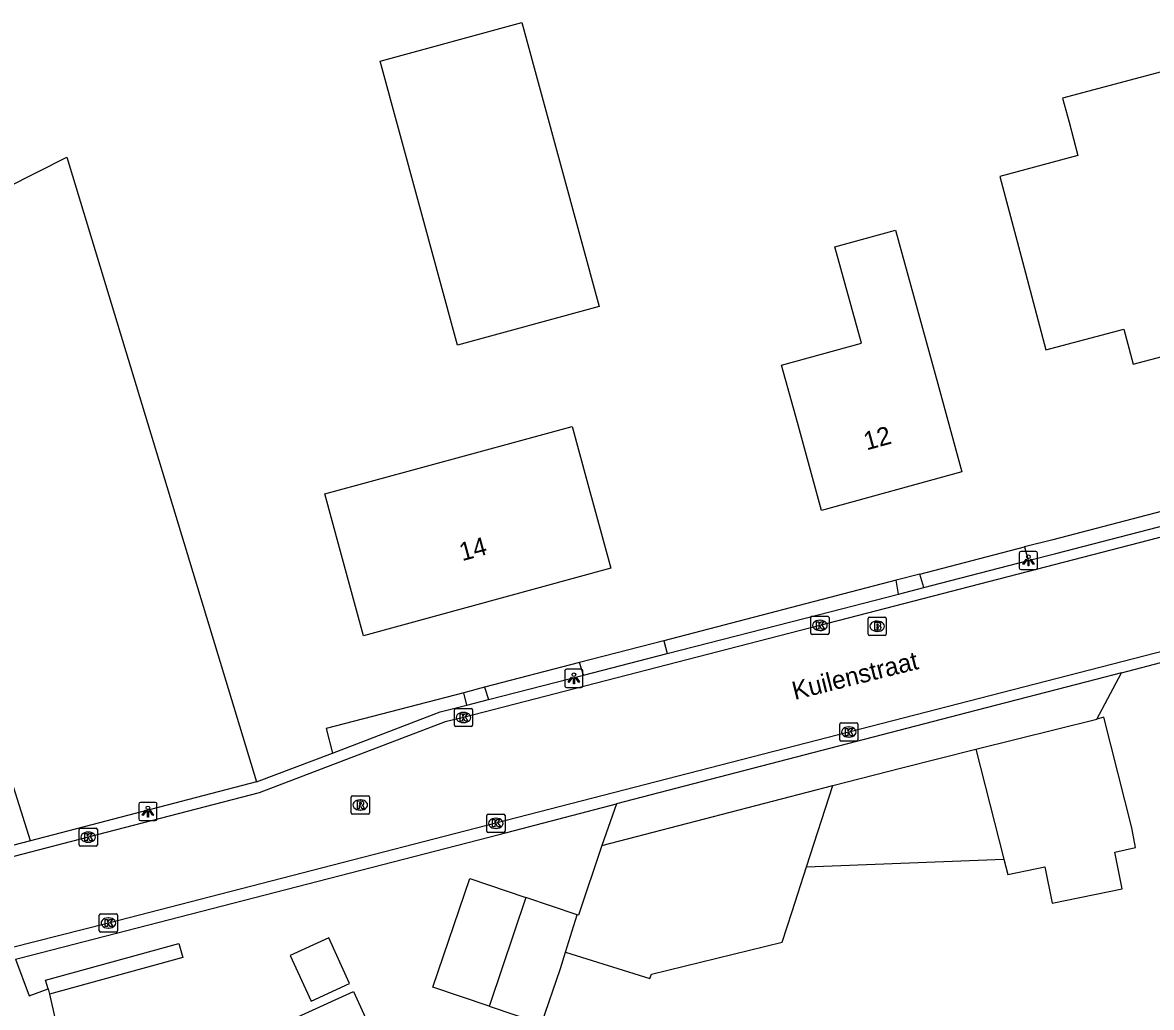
# Model space of a CAD drawing. Extents: x 162880 to 165536, y 384011 to 385179.
# Drawn here: x 163777.7 to 163839.6, y 384622 to 384676.1 of the extents above; entities that cross this region are included whole.
import ezdxf

# ---------------------------------------------------------------- set-up
doc = ezdxf.new("R2010")
doc.units = 0
for name, color, linetype in [('IMGEO_Brandkraan', 7, 'Continuous'), ('IMGEO_Groenvoorziening', 7, 'Continuous'), ('IMGEO_Haag', 7, 'Continuous'), ('IMGEO_Kolk', 7, 'Continuous'), ('IMGEO_Lichtpunt', 7, 'Continuous'), ('IMGEO_Openbare_ruimte_label', 7, 'Continuous'), ('IMGEO_Pand', 7, 'Continuous'), ('IMGEO_Pand_nummerreeks', 7, 'Continuous'), ('IMGEO_Rijbaan_lokaal_open', 7, 'Continuous'), ('IMGEO_Rioolput', 7, 'Continuous'), ('IMGEO_Voetpad_halfverhard', 7, 'Continuous'), ('IMGEO_Voetpad_open', 7, 'Continuous')]:
    doc.layers.add(name, color=color, linetype=linetype)

msp = doc.modelspace()

# ---------------------------------------------------------------- linework, layer by layer
at = {"layer": 'IMGEO_Brandkraan'}
for p, q in [((163824.029, 384642.526), (163824.029, 384643.378)), ((163824.104, 384643.452), (163824.956, 384643.452)), ((163824.517, 384643.232), (163824.542, 384643.232)), ((163825.03, 384643.378), (163825.03, 384642.526)), ((163824.54, 384642.672), (163824.515, 384642.672)), ((163824.956, 384642.452), (163824.104, 384642.452))]:
    msp.add_line(p, q, dxfattribs=at)
for points in [[(163824.029, 384642.526), (163824.029, 384643.378)], [(163824.104, 384643.452), (163824.956, 384643.452)], [(163824.377, 384643.152), (163824.377, 384642.752), (163824.59, 384642.752)], [(163824.608, 384643.152), (163824.377, 384643.152)], [(163825.03, 384643.378), (163825.03, 384642.526)], [(163824.556, 384643.071), (163824.502, 384643.071), (163824.502, 384642.995)], [(163824.502, 384642.995), (163824.555, 384642.995)], [(163824.564, 384642.919), (163824.502, 384642.919), (163824.502, 384642.838)], [(163824.502, 384642.838), (163824.564, 384642.838)], [(163824.956, 384642.452), (163824.104, 384642.452)]]:
    msp.add_lwpolyline(points, dxfattribs=at)
for centre, radius, start, end in [((163824.106, 384643.376), 0.0765, 91.55205, 178.44795), ((163824.106, 384643.376), 0.0765, 91.55205, 178.44795), ((163824.612, 384643.007), 0.145, 59.4692, 91.53667), ((163824.637, 384643.054), 0.0922, 285.51372, 58.15012), ((163824.954, 384643.376), 0.0765, 1.55205, 88.44795), ((163824.954, 384643.376), 0.0765, 1.55205, 88.44795), ((163824.106, 384642.528), 0.0765, 181.55205, 268.44795), ((163824.106, 384642.528), 0.0765, 181.55205, 268.44795), ((163824.557, 384643.033), 0.0379, 267.82845, 90.93552), ((163824.565, 384642.878), 0.0404, 269.87594, 90.50774), ((163824.596, 384643.003), 0.251, 268.66757, 293.53466), ((163824.642, 384642.862), 0.105, 301.31148, 78.98903), ((163824.954, 384642.528), 0.0765, 271.55205, 358.44795), ((163824.954, 384642.528), 0.0765, 271.55205, 358.44795)]:
    msp.add_arc(centre, radius, start, end, dxfattribs=at)
for centre, major_axis, ratio, start_param, end_param in [((163824.516, 384642.952), (-0.387, 0.002), 0.722429, 4.712389, 7.853982), ((163824.541, 384642.952), (-0.39, 0.002), 0.717154, 1.570796, 4.712389)]:
    msp.add_ellipse(centre, major_axis=major_axis, ratio=ratio, start_param=start_param, end_param=end_param, dxfattribs=at)
at = {"layer": 'IMGEO_Groenvoorziening'}
for points in [[(163776.799, 384667.029), (163780.094, 384668.687), (163790.492, 384634.412)], [(163778.093, 384631.181), (163768.177, 384662.661), (163766.054, 384662.013), (163765.695, 384663.191)], [(163808.212, 384640.956), (163803.003, 384639.602)]]:
    msp.add_lwpolyline(points, dxfattribs=at)
at = {"layer": 'IMGEO_Haag'}
for points in [[(163845.271, 384650.593), (163834.156, 384647.702), (163832.611, 384647.3)], [(163825.578, 384645.472), (163812.821, 384642.155)], [(163801.865, 384639.306), (163794.32, 384637.344), (163794.651, 384635.997)], [(163779.074, 384623.056), (163778.928, 384623.543), (163786.235, 384625.552), (163786.447, 384624.78), (163779.139, 384622.771)]]:
    msp.add_lwpolyline(points, dxfattribs=at)
at = {"layer": 'IMGEO_Kolk'}
for p, q in [((163820.889, 384642.572), (163820.889, 384643.424)), ((163820.964, 384643.498), (163821.816, 384643.498)), ((163821.377, 384643.278), (163821.402, 384643.278)), ((163821.89, 384643.424), (163821.89, 384642.572)), ((163821.816, 384642.498), (163820.964, 384642.498)), ((163821.4, 384642.718), (163821.375, 384642.718)), ((163801.341, 384637.521), (163801.341, 384638.373)), ((163801.416, 384638.447), (163802.268, 384638.447)), ((163801.829, 384638.227), (163801.854, 384638.227)), ((163802.342, 384638.373), (163802.342, 384637.521)), ((163801.852, 384637.667), (163801.827, 384637.667)), ((163822.474, 384636.723), (163822.474, 384637.575)), ((163822.549, 384637.649), (163823.401, 384637.649)), ((163823.475, 384637.575), (163823.475, 384636.723)), ((163802.268, 384637.447), (163801.416, 384637.447)), ((163822.962, 384637.429), (163822.987, 384637.429)), ((163823.401, 384636.649), (163822.549, 384636.649)), ((163822.985, 384636.869), (163822.96, 384636.869)), ((163803.119, 384631.717), (163803.119, 384632.569)), ((163803.194, 384632.643), (163804.046, 384632.643)), ((163804.12, 384632.569), (163804.12, 384631.717)), ((163803.607, 384632.423), (163803.632, 384632.423)), ((163780.763, 384630.957), (163780.763, 384631.809)), ((163780.838, 384631.883), (163781.69, 384631.883)), ((163781.251, 384631.663), (163781.276, 384631.663)), ((163781.764, 384631.809), (163781.764, 384630.957)), ((163804.046, 384631.643), (163803.194, 384631.643)), ((163803.63, 384631.863), (163803.605, 384631.863)), ((163781.69, 384630.883), (163780.838, 384630.883)), ((163781.274, 384631.103), (163781.249, 384631.103)), ((163781.868, 384626.247), (163781.868, 384627.099)), ((163781.943, 384627.173), (163782.795, 384627.173)), ((163782.869, 384627.099), (163782.869, 384626.247)), ((163782.379, 384626.393), (163782.354, 384626.393)), ((163782.356, 384626.953), (163782.381, 384626.953)), ((163782.795, 384626.173), (163781.943, 384626.173))]:
    msp.add_line(p, q, dxfattribs=at)
for points in [[(163820.889, 384642.572), (163820.889, 384643.424)], [(163820.964, 384643.498), (163821.816, 384643.498)], [(163821.21, 384643.198), (163821.333, 384643.198), (163821.333, 384643.047), (163821.463, 384643.198), (163821.627, 384643.198), (163821.481, 384643.047), (163821.634, 384642.798), (163821.482, 384642.798), (163821.397, 384642.962), (163821.333, 384642.895), (163821.333, 384642.798), (163821.21, 384642.798), (163821.21, 384643.198)], [(163821.89, 384643.424), (163821.89, 384642.572)], [(163821.816, 384642.498), (163820.964, 384642.498)], [(163801.341, 384637.521), (163801.341, 384638.373)], [(163801.416, 384638.447), (163802.268, 384638.447)], [(163801.662, 384638.147), (163801.785, 384638.147), (163801.785, 384637.996), (163801.915, 384638.147), (163802.079, 384638.147), (163801.933, 384637.996), (163802.086, 384637.747), (163801.934, 384637.747), (163801.849, 384637.911), (163801.785, 384637.844), (163801.785, 384637.747), (163801.662, 384637.747), (163801.662, 384638.147)], [(163802.342, 384638.373), (163802.342, 384637.521)], [(163822.474, 384636.723), (163822.474, 384637.575)], [(163822.549, 384637.649), (163823.401, 384637.649)], [(163823.475, 384637.575), (163823.475, 384636.723)], [(163802.268, 384637.447), (163801.416, 384637.447)], [(163822.795, 384637.349), (163822.918, 384637.349), (163822.918, 384637.198), (163823.048, 384637.349), (163823.212, 384637.349), (163823.066, 384637.198), (163823.219, 384636.949), (163823.067, 384636.949), (163822.982, 384637.113), (163822.918, 384637.046), (163822.918, 384636.949), (163822.795, 384636.949), (163822.795, 384637.349)], [(163823.401, 384636.649), (163822.549, 384636.649)], [(163803.119, 384631.717), (163803.119, 384632.569)], [(163803.194, 384632.643), (163804.046, 384632.643)], [(163804.12, 384632.569), (163804.12, 384631.717)], [(163803.44, 384632.343), (163803.563, 384632.343), (163803.563, 384632.192), (163803.693, 384632.343), (163803.857, 384632.343), (163803.711, 384632.192), (163803.864, 384631.943), (163803.712, 384631.943), (163803.627, 384632.107), (163803.563, 384632.04), (163803.563, 384631.943), (163803.44, 384631.943), (163803.44, 384632.343)], [(163780.763, 384630.957), (163780.763, 384631.809)], [(163780.838, 384631.883), (163781.69, 384631.883)], [(163781.084, 384631.583), (163781.207, 384631.583), (163781.207, 384631.432), (163781.337, 384631.583), (163781.501, 384631.583), (163781.355, 384631.432), (163781.508, 384631.183), (163781.356, 384631.183), (163781.271, 384631.347), (163781.207, 384631.28), (163781.207, 384631.183), (163781.084, 384631.183), (163781.084, 384631.583)], [(163781.764, 384631.809), (163781.764, 384630.957)], [(163804.046, 384631.643), (163803.194, 384631.643)], [(163781.69, 384630.883), (163780.838, 384630.883)], [(163781.868, 384626.247), (163781.868, 384627.099)], [(163781.943, 384627.173), (163782.795, 384627.173)], [(163782.869, 384627.099), (163782.869, 384626.247)], [(163782.189, 384626.873), (163782.312, 384626.873), (163782.312, 384626.722), (163782.442, 384626.873), (163782.606, 384626.873), (163782.46, 384626.722), (163782.613, 384626.473), (163782.461, 384626.473), (163782.376, 384626.637), (163782.312, 384626.57), (163782.312, 384626.473), (163782.189, 384626.473), (163782.189, 384626.873)], [(163782.795, 384626.173), (163781.943, 384626.173)]]:
    msp.add_lwpolyline(points, dxfattribs=at)
for centre, start, end in [((163820.966, 384643.422), 91.55205, 178.44795), ((163820.966, 384643.422), 91.55205, 178.44795), ((163821.814, 384643.422), 1.55205, 88.44795), ((163821.814, 384643.422), 1.55205, 88.44795), ((163820.966, 384642.574), 181.55205, 268.44795), ((163820.966, 384642.574), 181.55205, 268.44795), ((163821.814, 384642.574), 271.55205, 358.44795), ((163821.814, 384642.574), 271.55205, 358.44795), ((163801.418, 384638.371), 91.55205, 178.44795), ((163801.418, 384638.371), 91.55205, 178.44795), ((163802.266, 384638.371), 1.55205, 88.44795), ((163802.266, 384638.371), 1.55205, 88.44795), ((163801.418, 384637.523), 181.55205, 268.44795), ((163801.418, 384637.523), 181.55205, 268.44795), ((163802.266, 384637.523), 271.55205, 358.44795), ((163802.266, 384637.523), 271.55205, 358.44795), ((163822.551, 384637.573), 91.55205, 178.44795), ((163822.551, 384637.573), 91.55205, 178.44795), ((163823.399, 384637.573), 1.55205, 88.44795), ((163823.399, 384637.573), 1.55205, 88.44795), ((163822.551, 384636.725), 181.55205, 268.44795), ((163822.551, 384636.725), 181.55205, 268.44795), ((163823.399, 384636.725), 271.55205, 358.44795), ((163823.399, 384636.725), 271.55205, 358.44795), ((163803.196, 384632.567), 91.55205, 178.44795), ((163803.196, 384632.567), 91.55205, 178.44795), ((163804.044, 384632.567), 1.55205, 88.44795), ((163804.044, 384632.567), 1.55205, 88.44795), ((163780.84, 384631.807), 91.55205, 178.44795), ((163780.84, 384631.807), 91.55205, 178.44795), ((163781.688, 384631.807), 1.55205, 88.44795), ((163781.688, 384631.807), 1.55205, 88.44795), ((163803.196, 384631.719), 181.55205, 268.44795), ((163803.196, 384631.719), 181.55205, 268.44795), ((163804.044, 384631.719), 271.55205, 358.44795), ((163804.044, 384631.719), 271.55205, 358.44795), ((163780.84, 384630.959), 181.55205, 268.44795), ((163780.84, 384630.959), 181.55205, 268.44795), ((163781.688, 384630.959), 271.55205, 358.44795), ((163781.688, 384630.959), 271.55205, 358.44795), ((163781.945, 384627.097), 91.55205, 178.44795), ((163781.945, 384627.097), 91.55205, 178.44795), ((163782.793, 384627.097), 1.55205, 88.44795), ((163782.793, 384627.097), 1.55205, 88.44795), ((163781.945, 384626.249), 181.55205, 268.44795), ((163781.945, 384626.249), 181.55205, 268.44795), ((163782.793, 384626.249), 271.55205, 358.44795), ((163782.793, 384626.249), 271.55205, 358.44795)]:
    msp.add_arc(centre, 0.0765, start, end, dxfattribs=at)
for centre, major_axis, ratio, start_param, end_param in [((163821.376, 384642.998), (-0.387, 0.002), 0.722429, 4.712389, 7.853982), ((163821.401, 384642.998), (-0.39, 0.002), 0.717154, 1.570796, 4.712389), ((163801.828, 384637.947), (-0.387, 0.002), 0.722429, 4.712389, 7.853982), ((163801.853, 384637.947), (-0.39, 0.002), 0.717154, 1.570796, 4.712389), ((163822.961, 384637.149), (-0.387, 0.002), 0.722429, 4.712389, 7.853982), ((163822.986, 384637.149), (-0.39, 0.002), 0.717154, 1.570796, 4.712389), ((163803.606, 384632.143), (-0.387, 0.002), 0.722429, 4.712389, 7.853982), ((163803.631, 384632.143), (-0.39, 0.002), 0.717154, 1.570796, 4.712389), ((163781.25, 384631.383), (-0.387, 0.002), 0.722429, 4.712389, 7.853982), ((163781.275, 384631.383), (-0.39, 0.002), 0.717154, 1.570796, 4.712389), ((163782.355, 384626.673), (-0.387, 0.002), 0.722429, 4.712389, 7.853982), ((163782.38, 384626.673), (-0.39, 0.002), 0.717154, 1.570796, 4.712389)]:
    msp.add_ellipse(centre, major_axis=major_axis, ratio=ratio, start_param=start_param, end_param=end_param, dxfattribs=at)
at = {"layer": 'IMGEO_Lichtpunt'}
for p, q in [((163832.324, 384646.966), (163832.324, 384646.159)), ((163832.324, 384646.966), (163832.324, 384646.159)), ((163833.226, 384647.061), (163832.418, 384647.061)), ((163833.226, 384647.061), (163832.418, 384647.061)), ((163833.32, 384646.159), (163833.32, 384646.966)), ((163833.32, 384646.159), (163833.32, 384646.966)), ((163832.418, 384646.065), (163833.226, 384646.065)), ((163832.418, 384646.065), (163833.226, 384646.065)), ((163807.398, 384640.499), (163807.398, 384639.692)), ((163807.398, 384640.499), (163807.398, 384639.692)), ((163808.3, 384640.594), (163807.492, 384640.594)), ((163808.3, 384640.594), (163807.492, 384640.594)), ((163808.394, 384639.692), (163808.394, 384640.499)), ((163808.394, 384639.692), (163808.394, 384640.499)), ((163807.492, 384639.598), (163808.3, 384639.598)), ((163807.492, 384639.598), (163808.3, 384639.598)), ((163784.038, 384633.193), (163784.038, 384632.386)), ((163784.038, 384633.193), (163784.038, 384632.386)), ((163784.94, 384633.288), (163784.132, 384633.288)), ((163784.94, 384633.288), (163784.132, 384633.288)), ((163785.034, 384632.386), (163785.034, 384633.193)), ((163785.034, 384632.386), (163785.034, 384633.193)), ((163784.132, 384632.292), (163784.94, 384632.292)), ((163784.132, 384632.292), (163784.94, 384632.292))]:
    msp.add_line(p, q, dxfattribs=at)
for points in [[(163832.698, 384646.63), (163832.737, 384646.602), (163832.549, 384646.34), (163832.511, 384646.367), (163832.698, 384646.63)], [(163832.8, 384646.582), (163832.847, 384646.582), (163832.847, 384646.26), (163832.8, 384646.26), (163832.8, 384646.582)], [(163832.91, 384646.602), (163832.948, 384646.629), (163833.135, 384646.367), (163833.096, 384646.339), (163832.91, 384646.602)], [(163807.772, 384640.163), (163807.811, 384640.135), (163807.623, 384639.873), (163807.585, 384639.9), (163807.772, 384640.163)], [(163807.874, 384640.115), (163807.921, 384640.115), (163807.921, 384639.793), (163807.874, 384639.793), (163807.874, 384640.115)], [(163807.984, 384640.135), (163808.022, 384640.162), (163808.209, 384639.9), (163808.17, 384639.872), (163807.984, 384640.135)], [(163784.412, 384632.857), (163784.451, 384632.829), (163784.263, 384632.567), (163784.225, 384632.594), (163784.412, 384632.857)], [(163784.514, 384632.809), (163784.561, 384632.809), (163784.561, 384632.487), (163784.514, 384632.487), (163784.514, 384632.809)], [(163784.624, 384632.829), (163784.662, 384632.856), (163784.849, 384632.594), (163784.81, 384632.566), (163784.624, 384632.829)]]:
    msp.add_lwpolyline(points, dxfattribs=at)
for centre in [(163832.823, 384646.764), (163807.897, 384640.297), (163784.537, 384632.991)]:
    msp.add_circle(centre, 0.0994, dxfattribs=at)
for centre, start, end in [((163832.418, 384646.966), 90, 180), ((163832.418, 384646.966), 90, 180), ((163833.226, 384646.966), 0, 90), ((163833.226, 384646.966), 0, 90), ((163832.418, 384646.159), 180, 270), ((163832.418, 384646.159), 180, 270), ((163833.226, 384646.159), 270, 0), ((163833.226, 384646.159), 270, 360), ((163807.492, 384640.499), 90, 180), ((163807.492, 384640.499), 90, 180), ((163808.3, 384640.499), 0, 90), ((163808.3, 384640.499), 0, 90), ((163807.492, 384639.692), 180, 270), ((163807.492, 384639.692), 180, 270), ((163808.3, 384639.692), 270, 0), ((163808.3, 384639.692), 270, 360), ((163784.132, 384633.193), 90, 180), ((163784.132, 384633.193), 90, 180), ((163784.94, 384633.193), 0, 90), ((163784.94, 384633.193), 0, 90), ((163784.132, 384632.386), 180, 270), ((163784.132, 384632.386), 180, 270), ((163784.94, 384632.386), 270, 0), ((163784.94, 384632.386), 270, 360)]:
    msp.add_arc(centre, 0.0946, start, end, dxfattribs=at)
at = {"layer": 'IMGEO_Pand'}
for points in [[(163809.277, 384660.496), (163801.51, 384658.379), (163797.266, 384673.951), (163805.033, 384676.068), (163809.277, 384660.496)], [(163845.956, 384667.722), (163845.077, 384671.021), (163842.126, 384670.234), (163841.215, 384673.651), (163834.699, 384671.93), (163835.051, 384670.606), (163835.539, 384668.769), (163831.257, 384667.63), (163832.5, 384662.953), (163833.785, 384658.12), (163838.056, 384659.255), (163838.567, 384657.332), (163842.101, 384658.27), (163843.011, 384654.922), (163845.785, 384655.676), (163846.314, 384655.052), (163847.948, 384655.497), (163848.092, 384656.303), (163848.938, 384656.533), (163845.956, 384667.722)], [(163823.668, 384658.48), (163822.213, 384663.769), (163825.53, 384664.681), (163827.851, 384656.242), (163829.177, 384651.421), (163821.477, 384649.303), (163820.151, 384654.125), (163819.285, 384657.275), (163823.668, 384658.48)], [(163804.98, 384653.148), (163807.804, 384653.918), (163808.612, 384650.955), (163809.927, 384646.131), (163796.36, 384642.431), (163795.045, 384647.255), (163794.237, 384650.219), (163804.98, 384653.148)], [(163829.943, 384636.207), (163836.568, 384637.863)], [(163831.48, 384630.168), (163831.694, 384629.329), (163833.725, 384629.758), (163834.13, 384627.769), (163837.971, 384628.551), (163837.56, 384630.567), (163838.701, 384630.808), (163838.487, 384631.899), (163836.967, 384637.963), (163836.568, 384637.863)], [(163822.103, 384634.213), (163825.876, 384635.19), (163829.943, 384636.207)], [(163829.943, 384636.207), (163831.48, 384630.168)], [(163809.424, 384630.929), (163822.103, 384634.213)], [(163820.656, 384629.754), (163822.103, 384634.213)], [(163809.424, 384630.929), (163808.153, 384627.098), (163808.083, 384627.121)], [(163820.656, 384629.754), (163831.48, 384630.168)], [(163807.439, 384625.083), (163812.059, 384623.622), (163812.148, 384623.867), (163819.319, 384625.629), (163819.863, 384627.308), (163820.656, 384629.754)], [(163803.256, 384622.106), (163800.17, 384623.147), (163802.183, 384629.111), (163805.264, 384628.072)], [(163805.264, 384628.072), (163803.296, 384622.212), (163803.256, 384622.106)], [(163808.083, 384627.121), (163805.264, 384628.072)], [(163807.439, 384625.083), (163808.083, 384627.121)], [(163795.594, 384623.354), (163794.459, 384625.852), (163792.346, 384624.892), (163793.481, 384622.394), (163795.594, 384623.354)], [(163803.256, 384622.106), (163806.126, 384621.137), (163807.155, 384624.185), (163807.439, 384625.083)], [(163787.382, 384612.862), (163786.505, 384614.792), (163785.959, 384614.544), (163784.723, 384617.267), (163785.27, 384617.516), (163785.044, 384618.015), (163785.258, 384618.112), (163790.111, 384620.317), (163789.818, 384620.965), (163790.009, 384621.051), (163790.302, 384620.404), (163795.819, 384622.911), (163797.04, 384620.226), (163795.11, 384619.349), (163796.25, 384616.84)]]:
    msp.add_lwpolyline(points, dxfattribs=at)
at = {"layer": 'IMGEO_Rijbaan_lokaal_open'}
for points in [[(163866.861, 384654.779), (163860.553, 384653.15), (163840.936, 384648.051), (163821.39, 384642.998), (163801.842, 384637.947), (163800.838, 384637.703), (163790.63, 384633.82), (163781.264, 384631.383), (163775.331, 384629.849)], [(163867.902, 384648.771), (163862.099, 384647.248), (163842.2, 384642.092), (163822.975, 384637.149), (163803.62, 384632.143), (163782.369, 384626.673), (163777.04, 384625.303)]]:
    msp.add_lwpolyline(points, dxfattribs=at)
at = {"layer": 'IMGEO_Rioolput'}
for p, q in [((163795.682, 384632.723), (163795.682, 384633.575)), ((163795.757, 384633.649), (163796.609, 384633.649)), ((163796.17, 384633.429), (163796.195, 384633.429)), ((163796.683, 384633.575), (163796.683, 384632.723)), ((163796.609, 384632.649), (163795.757, 384632.649)), ((163796.193, 384632.869), (163796.168, 384632.869))]:
    msp.add_line(p, q, dxfattribs=at)
for points in [[(163795.682, 384632.723), (163795.682, 384633.575)], [(163795.757, 384633.649), (163796.609, 384633.649)], [(163796.271, 384633.347), (163796.019, 384633.349), (163796.019, 384632.949)], [(163796.197, 384633.268), (163796.143, 384633.268), (163796.143, 384633.187)], [(163796.143, 384633.187), (163796.195, 384633.187)], [(163796.683, 384633.575), (163796.683, 384632.723)], [(163796.609, 384632.649), (163795.757, 384632.649)], [(163796.019, 384632.949), (163796.143, 384632.949), (163796.143, 384633.111), (163796.154, 384633.111)], [(163796.201, 384633.082), (163796.272, 384632.949), (163796.412, 384632.949), (163796.347, 384633.075)]]:
    msp.add_lwpolyline(points, dxfattribs=at)
for centre, radius, start, end in [((163795.759, 384633.573), 0.0765, 91.55205, 178.44795), ((163795.759, 384633.573), 0.0765, 91.55205, 178.44795), ((163796.179, 384633.376), 0.19, 274.7715, 282.96867), ((163796.203, 384633.172), 0.0964, 77.00612, 93.18647), ((163796.217, 384633.229), 0.0378, 276.66336, 79.67722), ((163796.27, 384633.237), 0.109, 350.36119, 89.41601), ((163796.268, 384633.237), 0.112, 277.58423, 350.98172), ((163796.607, 384633.573), 0.0765, 1.55205, 88.44795), ((163796.607, 384633.573), 0.0765, 1.55205, 88.44795), ((163795.759, 384632.725), 0.0765, 181.55205, 268.44795), ((163795.759, 384632.725), 0.0765, 181.55205, 268.44795), ((163796.153, 384633.058), 0.0533, 26.02933, 88.69889), ((163796.252, 384633.022), 0.108, 29.51342, 73.79051), ((163796.607, 384632.725), 0.0765, 271.55205, 358.44795), ((163796.607, 384632.725), 0.0765, 271.55205, 358.44795)]:
    msp.add_arc(centre, radius, start, end, dxfattribs=at)
for centre, major_axis, ratio, start_param, end_param in [((163796.169, 384633.149), (-0.387, 0.002), 0.722429, 4.712389, 7.853982), ((163796.194, 384633.149), (-0.39, 0.002), 0.717154, 1.570796, 4.712389)]:
    msp.add_ellipse(centre, major_axis=major_axis, ratio=ratio, start_param=start_param, end_param=end_param, dxfattribs=at)
at = {"layer": 'IMGEO_Voetpad_halfverhard'}
for points in [[(163826.868, 384645.807), (163832.611, 384647.3)], [(163832.611, 384647.3), (163832.817, 384646.563)]]:
    msp.add_lwpolyline(points, dxfattribs=at)
at = {"layer": 'IMGEO_Voetpad_open'}
for points in [[(163832.817, 384646.563), (163834.326, 384646.952), (163845.48, 384649.838)], [(163837.924, 384640.399), (163842.315, 384641.54), (163868.031, 384648.176)], [(163827.094, 384645.08), (163827.515, 384645.189), (163832.817, 384646.563)], [(163826.868, 384645.807), (163825.578, 384645.472)], [(163827.094, 384645.08), (163826.868, 384645.807)], [(163825.707, 384644.721), (163825.578, 384645.472)], [(163825.707, 384644.721), (163827.094, 384645.08)], [(163813.02, 384641.452), (163821.297, 384643.58), (163825.707, 384644.721)], [(163812.821, 384642.155), (163808.212, 384640.956)], [(163812.821, 384642.155), (163813.02, 384641.452)], [(163808.431, 384640.273), (163813.02, 384641.452)], [(163808.431, 384640.273), (163808.212, 384640.956)], [(163803.208, 384638.93), (163808.431, 384640.273)], [(163837.924, 384640.399), (163836.514, 384640.033), (163829.437, 384638.195), (163810.24, 384633.209)], [(163836.568, 384637.863), (163837.924, 384640.399)], [(163803.003, 384639.602), (163801.865, 384639.306)], [(163803.003, 384639.602), (163803.208, 384638.93)], [(163802.034, 384638.628), (163801.865, 384639.306)], [(163802.034, 384638.628), (163803.208, 384638.93)], [(163794.651, 384635.997), (163800.564, 384638.25), (163802.034, 384638.628)], [(163790.492, 384634.412), (163794.651, 384635.997)], [(163790.492, 384634.412), (163778.093, 384631.181)], [(163777.269, 384624.69), (163777.499, 384624.749), (163803.803, 384631.537), (163810.24, 384633.209)], [(163810.24, 384633.209), (163809.424, 384630.929)], [(163778.093, 384631.181), (163775.122, 384630.407)], [(163777.269, 384624.69), (163778.028, 384622.671), (163779.074, 384623.056)], [(163779.074, 384623.056), (163779.139, 384622.771)], [(163779.139, 384622.771), (163779.71, 384620.265)]]:
    msp.add_lwpolyline(points, dxfattribs=at)

# ---------------------------------------------------------------- texts
at = {"layer": 'IMGEO_Openbare_ruimte_label'}
msp.add_text('Kuilenstraat', height=1, rotation=14.06404, dxfattribs=at).set_placement((163820.006, 384638.904))
at = {"layer": 'IMGEO_Pand_nummerreeks'}
for s, rotation, p in [('12', 15.37971, (163823.947, 384652.596)), ('14', 15.25476, (163801.77, 384646.519))]:
    msp.add_text(s, height=1, rotation=rotation, dxfattribs=at).set_placement(p)

doc.saveas('drawing.dxf')
